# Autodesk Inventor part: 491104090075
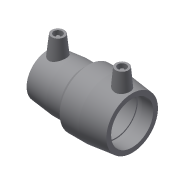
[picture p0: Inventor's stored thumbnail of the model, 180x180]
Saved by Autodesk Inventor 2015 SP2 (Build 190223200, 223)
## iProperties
Created: 2017-06
Part Number: 491104090075
Material: Generic
Description: PLASSON REDUCING COUPLER 90-75
Document SubType Name: Modeling
Designer: KIM
Mass: 54.8237 g
Surface Area: 155.252 cm^2
Volume: 54.8237 cm^3
Density: 1 g/cm^3
Appearance: Default
Author: KIM
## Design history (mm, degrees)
derived "491104.ipt"
feature "Solid1::491104.ipt"
tag "TaggingFeature1"
body "Solid1"
other parameters: "d_1" = 75, "L_" = 143, "L_2" = 61, "D_1" = 98, "A_1" = 67, "d_2" = 12, "L_1" = 71, "A_" = 78, "D_" = 116, "d0" = 143, "d2" = 98, "d3" = 61, "d4" = 36.6, "d5" = 88.2, "d7" = 75, "d8" = 168 deg, "d10" = 24.4, "d11" = 8.13333, "d13" = 143, "d14" = 17.6296, "d15" = 61, "d18" = 75, "d19" = 3.05, "d20" = 168 deg, "d22" = 108.92847, "d25" = 135 deg, "d29" = 67, "d30" = 15, "d31" = 57.2, "d34" = 6 deg, "d35" = 15, "d38" = 25.75, "d39" = 5 deg, "d41" = 4, "d42" = 14, "d43" = 0, "d45" = 4, "d46" = 14, "d47" = 0, "d48" = 98, "d50" = 116, "d52" = 67.5, "d53" = 28.4, "d54" = 9.46667, "d55" = 168 deg, "d56" = 42.6, "d57" = 71, "d58" = 104.4, "d59" = 3.05, "d60" = 135 deg, "d61" = 78, "d62" = 15, "d64" = 4, "d66" = 5 deg, "d67" = 14, "d68" = 0, "d69" = 57.2, "d70" = 98, "d71" = 116, "d73" = 109.04, "d76" = 3.05, "d77" = 168 deg, "d79" = 3.05, "d80" = 71, "d81" = 67.5, "d82" = 92.12, "d83" = 120 deg, "d88" = 15, "d89" = 28.5, "d90" = 5 deg, "d92" = 4, "d93" = 14, "d94" = 0, "d95" = 3, "d96" = 0, "d97" = 3, "d98" = 0, "d99" = 17.69, "d100" = 4.4225, "d101" = 89.3564, "d102" = 20 deg, "d103" = 20.59, "d104" = 5.1475, "d105" = 105.7688, "d106" = 3.60705, "d107" = 3, "d108" = 0, "d109" = 3, "d110" = 0
